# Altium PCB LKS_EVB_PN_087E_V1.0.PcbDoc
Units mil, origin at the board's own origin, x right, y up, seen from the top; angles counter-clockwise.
Board outline 1880 x 1275 mil, 2 copper layers (Top Layer, Bottom Layer); 38 components, 28 nets, 115 pads, 60 vias.
Unrouted connection lines stored in the file: 3.
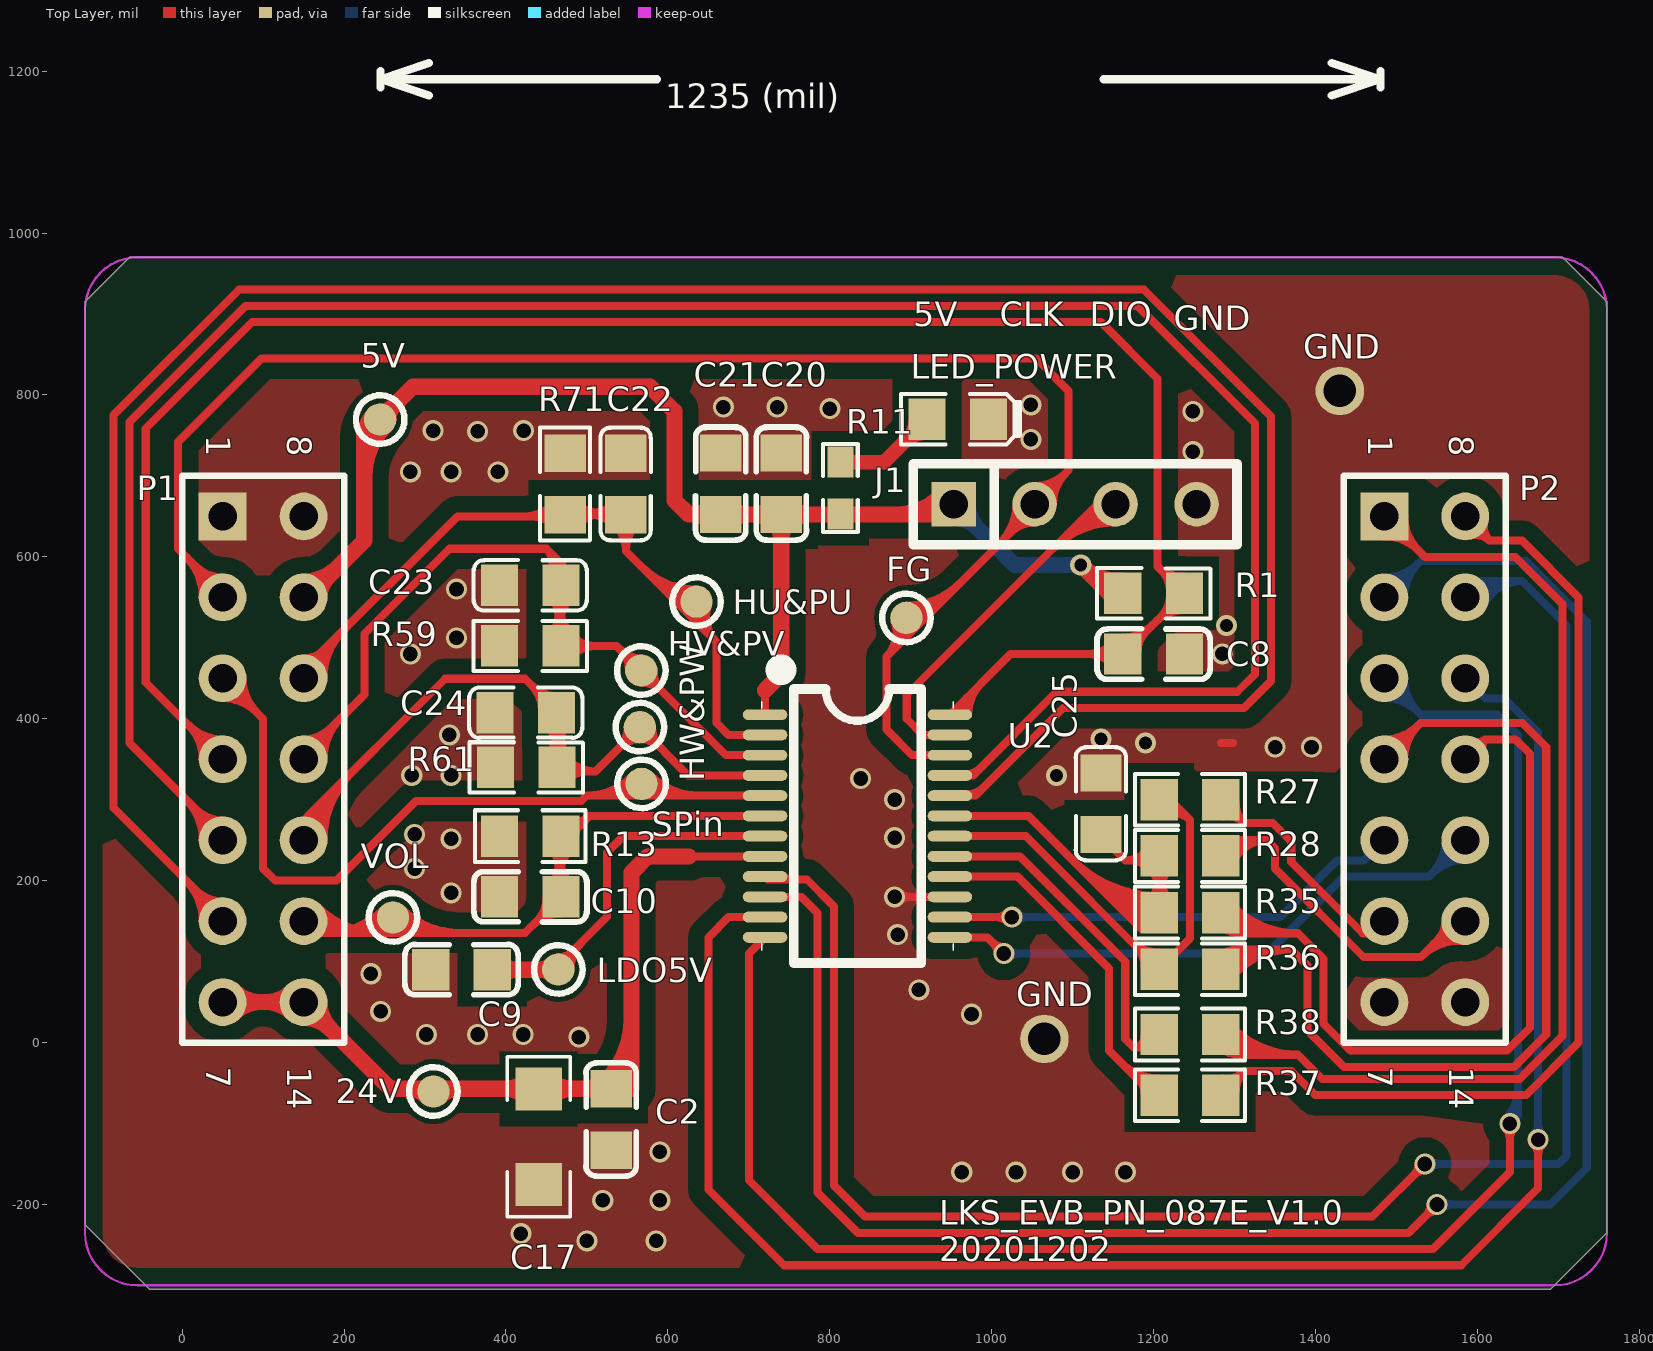
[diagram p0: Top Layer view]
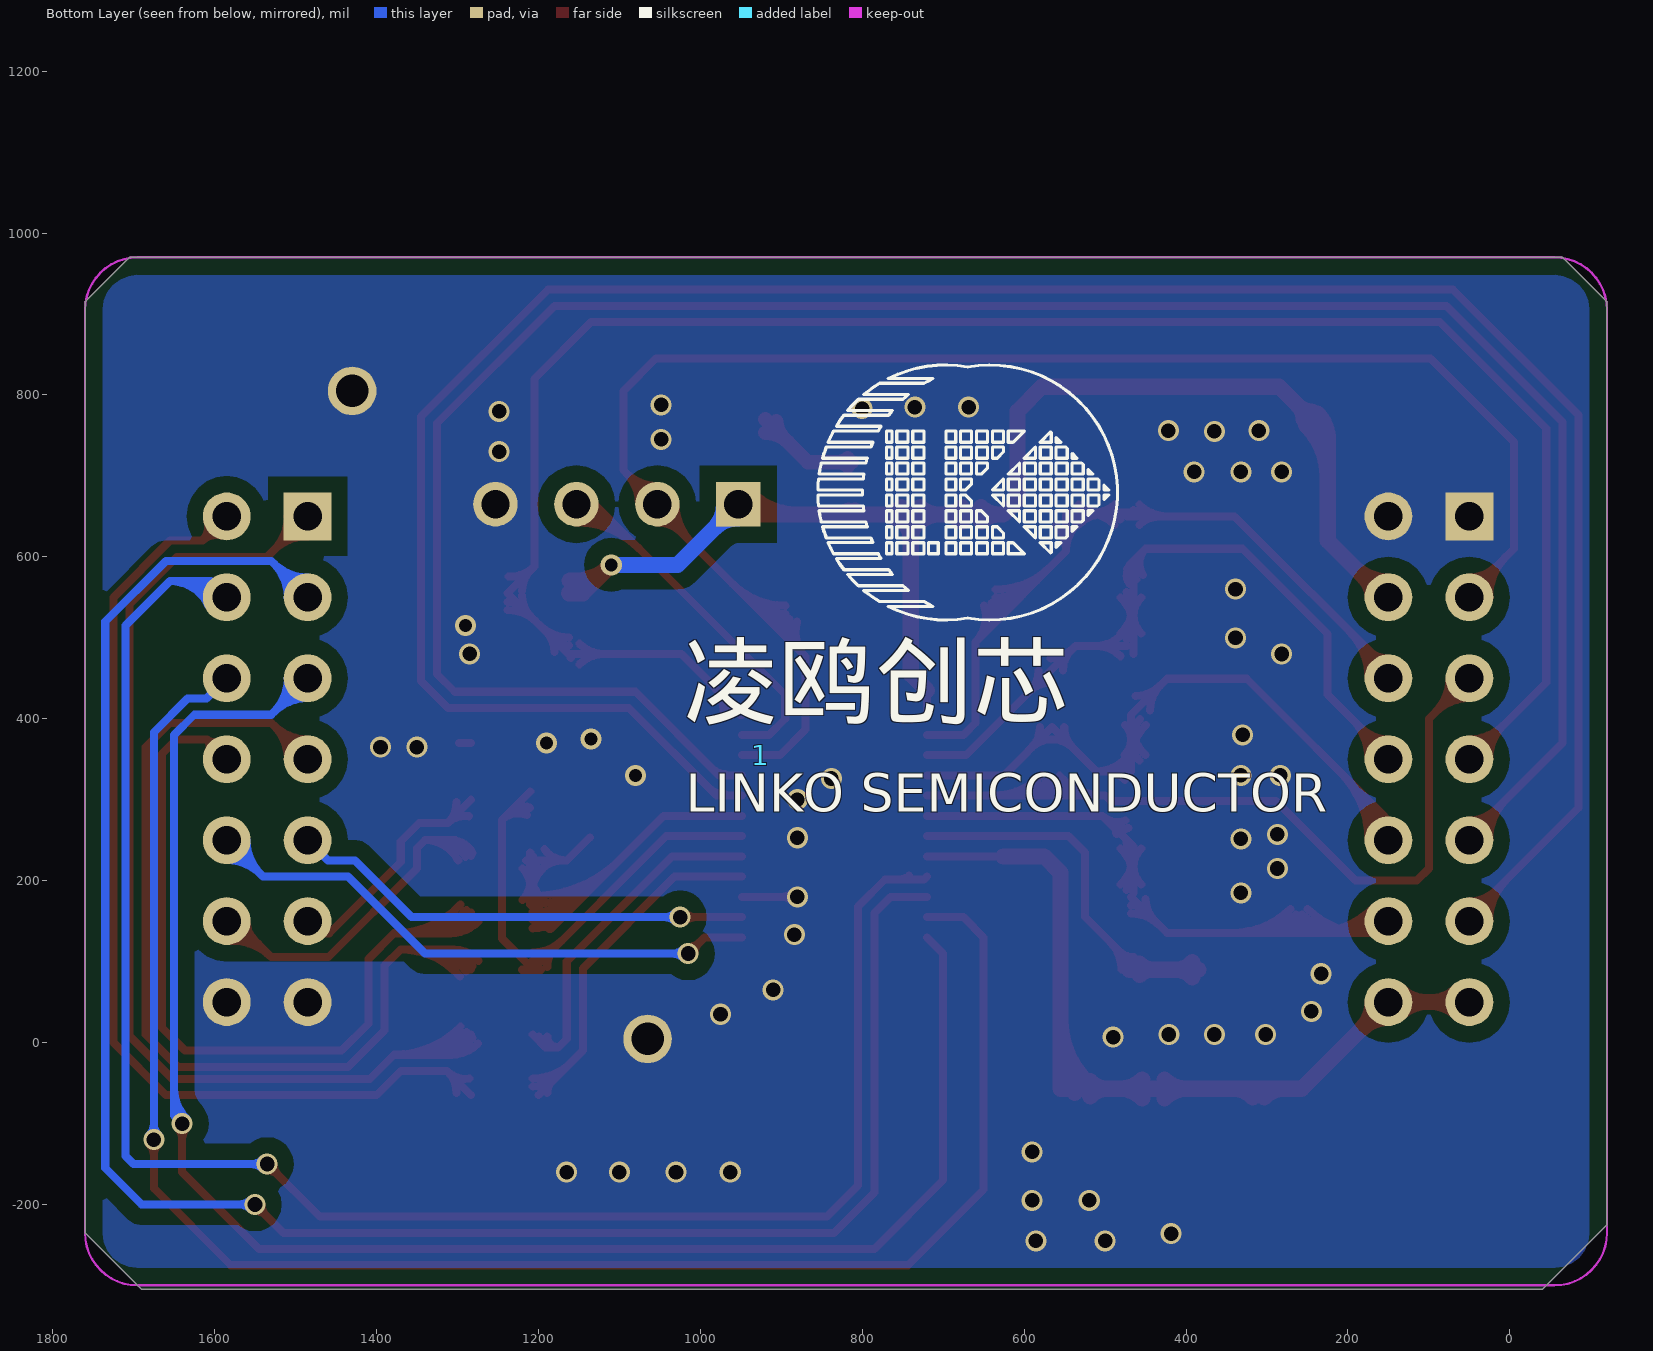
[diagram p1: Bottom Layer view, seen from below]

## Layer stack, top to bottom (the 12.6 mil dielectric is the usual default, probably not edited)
Top Layer: signal copper 1.4
Dielectric: dielectric 12.6, FR-4, Dk 4.8
Bottom Layer: signal copper 1.4

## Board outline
-120,-225 -40,-305 1690,-305 1760,-235 1760,915 1705,970 -65,970 -120,915

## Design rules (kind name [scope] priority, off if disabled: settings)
Clearance Clearance_1 [INPolygon] p1: gap=20
Clearance [All] p2: gap=10
ComponentClearance [All] p1: gap=0 collisioncheckmode=3 verticalgap=0 showdistances=FALSE
FabricationTestpoint [(IsPad And (OnTopLayer Or OnBottomLayer))] p1: side=3 testpointundercomponent=TRUE minsize=40 maxsize=100 preferedsize=60 minholesize=0 maxholesize=40 preferedholesize=32 testpointgrid=1 allowsidetop=TRUE allowsidebottom=TRUE usegrid=TRUE gridtolerance=0.01
PolygonConnect [All] p1: connectstyle=Direct reliefconductorwidth=20 reliefentries=4 polygonreliefangle="90 Angle"
RoutingVias [All] p1: holewidth=28 width=50 viastyle="Through Hole" minholewidth=28 minwidth=50 maxholewidth=28 maxwidth=50
SilkscreenOverComponentPads [All] p1: minsilkscreentomaskgap=10
SolderMaskExpansion [All] p1: expansion=4
Width [All] p1: maxlimit=300 minlimit=1 preferedwidth=10
25 further rules are at their usual default settings.

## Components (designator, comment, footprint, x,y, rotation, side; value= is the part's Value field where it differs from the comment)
1 "LKS_sign" LKS_LOGO2 925,355 r180 bottom
5V "TestP" TP-40 245,770 r0 top
24V "TestP" TP-40 310,-60 r90 top
C2 "100nF" 0805C 530,-95 r270 top
C8 "100nF" 0805C 1200,480 r0 top
C9 "1uF/10V" 0805C 345,90 r180 top
C10 "100nF" 0805C 430,180 r180 top
C17 "10uF/50V" 1206 440,-175 r90 top
C20 "100nF" 0805C 740.04,690.32 r90 top
C21 "10uF/10V" 0805C 665.04,690.32 r90 top
C22 "1nF/16V" 0805C 548,690 r270 top
C23 "1nF/16V" 0805C 430,565 r0 top
C24 "1nF/16V" 0805C 424.51,407.59 r0 top
C25 "100pF/50V" 0805C 1135,295 r270 top
FG "TestP" TP-40 895,525 r0 top
HU&PU "TestP" TP-40 635,545 r90 top
HV&PV "TestP" TP-40 566.72,460 r90 top
HW&PW "TestP" TP-40 565,390 r90 top
J1 "SWD" SIP4-2.5 1103,665 r0 top
LDO5V "TestP" TP-40 465,90 r270 top
LED_POWER "" 0805D 958,770 r0 top
P1 "Header 7X2A" HDR2X7_CEN 50,650 r270 top locked
P2 "Header 7X2A" HDR2X7_CEN 1485,650 r270 top locked
R1 "20K" 0805R 1200,555 r0 top
R11 "3.3K" 0603R 813,685 r270 top
R13 "3.3K" 0805R 430,255 r180 top
R27 "1K" 0805R 1245,300 r0 top
R28 "1K" 0805R 1245,230.59 r0 top
R35 "1K" 0805R 1245,160.59 r180 top
R36 "1K" 0805R 1245,90.59 r180 top
R37 "1K" 0805R 1245,-65 r180 top
R38 "1K" 0805R 1245,10 r180 top
R59 "20K 1%" 0805R 430,490 r0 top
R61 "3.3K" 0805R 425,340 r0 top
R71 "3.3K" 0805R 473,690 r270 top
SPin "TestP" TP-40 567.11,320 r90 top
U2 "LKS087E" LINKO-087 720,405 r270 top
VOL "TestP" TP-40 260,155 r90 top

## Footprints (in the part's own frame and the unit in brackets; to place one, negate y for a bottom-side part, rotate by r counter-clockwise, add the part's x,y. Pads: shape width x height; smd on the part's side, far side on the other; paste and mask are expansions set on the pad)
0603R [mil]
  rect 38x32 smd: 1(-32,0) 2(32,0)
  silkscreen extent -55,-22 55,22, body extent -31,-16 32,16, height 18
0805C [mil]
  rect 46x51.18 smd: 1(-38,0) 2(38,0)
  silkscreen extent -70,-31 70,31
0805D [mil]
  rect 46x51.18 smd: 1(-38,0) 2(38,0)
  silkscreen extent -70,-31 77,31, body extent -39,-25 39,25, height 22
0805R [mil]
  rect 46x51.18 smd: 1(-38,0) 2(38,0)
  silkscreen extent -70,-31 70,31, body extent -39,-25 39,25, height 22
1206 [mm]
  rect 1.35x1.45 smd: 1(-0.01,-0.01) 2(2.99,-0.01)
  silkscreen extent -1.02,-1 4,0.98
HDR2X7_CEN [mm] "Connector; Header; 7x2 Position"
  rect 1.5x1.5 hole 0.9: 1(0,0)
  round 1.5 hole 0.9: 2(2.54,0) 3(5.08,0) 4(7.62,0) 5(10.16,0) 6(12.7,0) 7(15.24,0) 8(0,2.54) 9(2.54,2.54) 10(5.08,2.54) 11(7.62,2.54) 12(10.16,2.54) 13(12.7,2.54) 14(15.24,2.54)
  silkscreen extent -1.27,-1.27 16.51,3.81
LINKO-087 [mm]
  oval 0.34x1.4 smd: 1(0,0) 2(0.635,0) 3(1.27,0) 4(1.905,0) 5(2.54,0) 6(3.175,0) 7(3.81,0) 8(4.445,0) 9(5.08,0) 10(5.715,0) 11(6.35,0) 12(6.985,0) 13(6.985,5.8) 14(6.35,5.8) 15(5.715,5.8) 16(5.08,5.8) 17(4.445,5.8) 18(3.81,5.8) 19(3.175,5.8) 20(2.54,5.8) 21(1.905,5.8) 22(1.27,5.8) 23(0.635,5.8) 24(0,5.8)
  silkscreen extent -1.51,-0.1 7.79,5.9
LKS_LOGO2 [mil] "标?"
  silkscreen extent 70,167 440,482
SIP4-2.5 [mil]
  rect 55x55 hole 35: 1(-150,0)
  round 55 hole 35: 2(-50,0) 3(50,0) 4(150,0)
  silkscreen extent -200,-50 200,50
TP-40 [mil] "测?"
  round 40 smd: 1(-0.39,-0.39)
  silkscreen extent -30,-30 30,30

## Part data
C2 C10 C17: library part CAP, "Capacitor"
C8 C20 C21 C22 C23 C24 C25: library part C, "Capacitor"
C9: library part C, "Cap"
J1: library part "Header 4", "Header, 4-Pin"
LED_POWER: library part LED2, "Typical RED, GREEN, YELLOW, AMBER GaAs LED"
P1 P2: "Header, 7-Pin, Dual row"
R1 R27 R28 R35 R36 R37 R38: library part RES2-1
R11 R13: library part Res2, "Resistor"
R59 R61 R71: library part RES/1

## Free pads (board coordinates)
  round 60 hole 40: 6(1065,4.61) 7(1430,805)

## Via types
v1: diameter 25.98, hole 17.99, Top Layer to Bottom Layer, 55 vias
v2: diameter 26, hole 16, Top Layer to Bottom Layer, 5 vias

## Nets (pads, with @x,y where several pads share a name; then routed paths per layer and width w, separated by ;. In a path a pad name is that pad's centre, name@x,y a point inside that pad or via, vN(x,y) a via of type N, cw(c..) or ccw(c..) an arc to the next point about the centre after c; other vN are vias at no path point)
5V: 5V.1 C20.1 C21.1 J1.1 P1.9 R1.1 R11.2 U2.1 | length 2374
  Top Layer w10: U2.1 720,435
  Top Layer w20: P1.9@150,569.53 ccw(c150,628.74) 191.87,586.87 ; P1.9@155,550 225,620 225,750 285,810 578,810 608,780 608,670 625.69,652.32 C21.1 C20.1 940.32,652.32 J1.1 ; P1.9@169.53,550 cw(c204.6,550) 179.8,574.8 ; 225,698.13 cw(c316.08,698.13) 5V.1@251.68,762.54 ; 225,746.41 cw(c267.8,746.41) 5V.1@237.54,776.68 ; 5V.1@234.61,769.61 cw(c210.46,769.61) 227.54,752.54 cw(c244.61,735.46) 5V.1@244.61,759.61 ; 5V.1@244.61,779.61 ccw(c244.61,803.75) 261.68,786.68 ccw(c278.75,769.61) 5V.1@254.61,769.61 ; C21.1@653.26,643.12 ccw(c631.06,620.93) 631.06,652.32 ccw(c631.06,683.7) C21.1@653.26,661.51 ; C21.1@676.82,643.12 cw(c699.01,620.93) 699.01,652.32 cw(c699.01,683.7) C21.1@676.82,661.51 ; 720,435 740,455 C20.1@740,652 ; C20.1@728.26,643.12 ccw(c706.06,620.93) 706.06,652.32 ccw(c706.06,683.7) C20.1@728.26,661.51 ; C20.1@730.85,643.12 cw(c708.75,621.03) 740,621.03 ; 740,620.84 cw(c771.52,620.84) C20.1@749.23,643.12 ; C20.1@751.82,643.12 cw(c774.01,620.93) 774.01,652.32 cw(c774.01,683.7) C20.1@751.82,661.51 ; 796.86,652.32 ccw(c796.86,669.14) R11.2@808.76,657.24 ; R11.2@817.24,657.24 ccw(c829.14,669.14) 829.14,652.32 ; 880.13,652.32 ccw(c880.13,737.87) J1.1@940.63,677.37 ; J1.1@928.41,652.32 ccw(c928.41,689.59) J1.1@954.77,663.23 ; R1.1@1161.22,570.57 cw(c1157.2,637.2) v2(1110,590) 1145,555 R1.1
  Bottom Layer w20: J1.1@953,647.5 cw(c953,605.25) 982.87,635.13 cw(c1012.75,665) J1.1@970.5,665 ; J1.1 1028,590 v2(1110,590)
24V_MCU: 24V.1 C2.1 C17.2 P1.7 P1.14 U2.8 | length 1574.5
  Top Layer w10: 625.69,230 U2.8
  Top Layer w20: P1.7 P1.14 257,-57 555,-57 555,210 575,230 625.69,230 ; P1.7@63.81,36.19 cw(c97.14,2.86) 97.14,50 cw(c97.14,97.14) P1.7@63.81,63.81 ; P1.14@136.19,36.19 ccw(c102.86,2.86) 102.86,50 ccw(c102.86,97.14) P1.14@136.19,63.81 ; P1.14@150,30.47 cw(c150,-16.67) 183.34,16.66 cw(c216.67,50) P1.14@169.53,50 ; 278.06,-57 cw(c278.06,-92.73) 24V.1@303.32,-67.46 ; 24V.1@317.46,-67.46 cw(c342.73,-92.73) 342.73,-57 ; 397.72,-57 cw(c397.72,-97.99) C17.2@426.71,-69 ; 399.1,-57 ccw(c399.1,-17.95) C17.2@426.71,-45.56 ; C17.2@454.08,-69 cw(c483.06,-97.99) 483.06,-57 ; C17.2@454.08,-45.56 ccw(c481.69,-17.95) 481.69,-57 ; C2.1@518.22,-66.19 ccw(c496.02,-88.38) 496.02,-57 ccw(c496.02,-25.62) C2.1@518.22,-47.81 ; C2.1@523.4,-47.81 ccw(c447.1,28.49) 555,28.49 ; C2.1@537.54,-61.95 ccw(c495.39,-19.8) 555,-19.8
FG: FG.1 J1.2 P1.2 U2.22 | length 2628
  Top Layer w10: 4.59,600.41 cw(c-45.81,550) P1.2@25.47,550 ; 16.66,588.34 ccw(c50,621.67) P1.2@50,574.53 ; 21.66,583.34 cw(c-11.67,550) P1.2@35.47,550 ; P1.2@55,550 -5,610 -5,741.86 98.14,845 1055,845 1095,805 1095,707 J1.2 ; FG.1@880.35,519.95 cw(c839.96,506.76) 870,476.72 ; 881.52,488.24 ccw(c857.33,512.43) FG.1@889.85,523.05 ; 893.04,499.76 ccw(c874.69,518.1) FG.1@899.36,526.16 ; FG.1@894.61,519.61 ccw(c894.61,563.75) 925.82,532.54 ; FG.1@894.61,529.61 ccw(c894.61,597.89) 942.89,549.61 ; FG.1@894.61,539.61 ccw(c894.61,632.03) 959.96,566.68 ; U2.22 901.72,355 870,386.72 870,476.72 ; 1010.85,617.57 ccw(c963.42,665) J1.2@1030.5,665 ; 1023.61,630.33 cw(c1053,600.94) J1.2@1053,642.5 ; 1027.92,634.64 ccw(c997.57,665) J1.2@1040.5,665 ; J1.2@1053,656.28 1049.57,656.28 870,476.72 ; J1.2@1053,677.5 ccw(c1053,707.68) 1074.34,686.34 ccw(c1095.68,665) J1.2@1065.5,665 ; J1.2@1053,687.5 ccw(c1053,741.82) 1091.41,703.41 ccw(c1129.82,665) J1.2@1075.5,665
G: P2.1 P2.4 P2.13 R28.2 R36.1 R38.1 | length 3916.6
  Top Layer w10: R36.1@1273.92,101.02 cw(c1304.45,74.66) R36.1@1304.45,115 ; R38.1@1274.37,-0.93 ccw(c1307.54,31.14) 1307.54,-15 ; R28.2@1281.22,234.09 cw(c1307.26,220.74) 1307.26,250 ; R36.1@1281.49,94.49 cw(c1326.3,55.79) 1326.3,115 ; R38.1@1281.56,6.02 ccw(c1331.12,53.94) 1331.12,-15 ; R38.1 1308,-15 ; R36.1 1307.41,115 ; R28.2 1302.41,250 1340,250 ; R38.1@1288.03,-9.87 cw(c1293.68,-29.32) 1308,-15 ; R36.1@1288.41,110.35 ccw(c1294.08,128.33) 1307.41,115 ; R38.1@1288.75,12.97 ccw(c1354.7,76.74) 1354.7,-15 ; R36.1@1289.05,87.95 cw(c1348.15,36.92) 1348.15,115 ; R28.2@1290.12,229.53 cw(c1323.63,212.34) 1323.63,250 ; R38.1@1295.94,19.92 ccw(c1378.28,99.53) 1378.28,-15 ; R36.1@1296.62,81.42 cw(c1370,18.06) 1370,115 ; R28.2@1299.02,224.96 cw(c1340,203.94) 1340,250 ; R36.1@1300.84,95.57 cw(c1323.76,98.65) 1307.41,115 ; R38.1@1300.88,5.37 ccw(c1325.56,2.56) 1308,-15 ; P2.4 1529.53,394.53 1655.47,394.53 1685,365 1685,10 1645,-30 1435,-30 1390,15 1390,95 1370,115 ; P2.4@1485,364.53 ccw(c1485,399.6) 1509.8,374.8 ccw(c1534.6,350) P2.4@1499.53,350 ; P2.4@1485,374.53 ccw(c1485,433.74) 1526.87,391.87 ccw(c1568.74,350) P2.4@1509.53,350 ; P2.1@1485,625.47 cw(c1485,566.26) 1526.87,608.13 cw(c1568.74,650) P2.1@1509.53,650 ; P2.1@1485,635.47 cw(c1485,600.4) 1509.8,625.2 cw(c1534.6,650) P2.1@1499.53,650 ; P2.1 1535,600 1646.72,600 1705,541.72 1705,8.28 1651.72,-45 1408.28,-45 1378.28,-15 ; 1545.02,120.97 cw(c1580.43,85.57) P2.13@1583.97,135.51 ; 1550.87,126.81 ccw(c1527.68,150) P2.13@1560.47,150 ; P2.13@1583.26,125.53 ccw(c1578.38,56.63) 1529.53,105.47 ; P2.13 1574.06,150 1529.53,105.47 ; 1307.41,115 1370,115 ; 1308,-15 1378.28,-15 ; 1340,250 1350,240 1350,215 1459.53,105.47 1529.53,105.47
GND: C2.2 C8.2 C9.2 C10.2 C17.1 C20.2 C21.2 C22.1 C23.1 C24.1 C25.1 J1.4 LED_POWER.2 P1.1 P1.8 P2.6 P2.7 P2.14 pad.6 pad.7 R13.2 R27.2 R59.1 R61.1 R71.1 U2.15 | length 462.5
  Top Layer w10: v1(880.13,180) U2.15 ; v1@885.78,174.35 cw(c899.42,160.71) 899.42,180 cw(c899.42,199.29) v1@885.78,185.65 ; R27.2 1311.82,271.18 ; 1283,370 1298.28,370 ; R27.2@1285.82,279.63 cw(c1290.53,249.89) 1311.82,271.18 ; R27.2@1301,297.37 ccw(c1337.93,297.3) 1311.82,271.18 ; P2.6 1470,135 1458.28,135 1370,223.28 1370,248.28 1347.1,271.18 1311.82,271.18
  other v1: 500,-245 585.43,-245 418.46,-235.9 519.51,-195 590,-195 963,-160 1030,-160 1100,-160 1165,-160 590,-135 490,6.74 301.58,10 365,10 421.08,10 975,35 245.17,38.57 910,65 233.18,85 883.69,133.45 332.17,185 287.2,215 332.24,251.63 880.13,253.02 287.2,257.11 880,300 838.02,326.18 283.58,330 332.17,330 1350,365 1395,365 330,380 281.87,480 1285,480.13 338.9,500 338.9,560 281.87,705 332.17,705 390,705 1248.44,730 1048.36,745 365,755 310,756 421.86,756 1248.44,779.74 800,783.04 668.41,785 735,785 1048.36,787.83
  other v2: 1080,330 1190,370 1135,375 1290,515
HU&PU: C22.2 HU&PU.1 P1.10 R71.2 U2.2 | length 1653.4
  Top Layer w10: P1.10@150,460 340,650 R71.2@473,650 ; P1.10@150,474.53 ccw(c150,509.6) 174.8,484.8 ; P1.10@164.53,450 cw(c223.74,450) 181.87,491.87 ; P1.10@174.53,450 cw(c257.88,450) 198.94,508.94 ; 422.13,650 ccw(c422.13,700.28) R71.2@457.68,664.73 ; 431.78,650 cw(c431.78,613.37) R71.2@457.68,639.27 ; 446.27,650 ccw(c446.27,676.14) R71.2@464.75,657.66 ; R71.2@463,655 C22.2@543,655 ; R71.2@481.25,646.34 cw(c502.15,625.44) 502.15,655 ; R71.2@488.32,639.27 cw(c526.29,601.3) C22.2@526.29,655 ; R71.2@488.32,664.73 ccw(c511.8,688.21) 511.8,655 ; R71.2@494.71,655 cw(c494.71,601.3) C22.2@532.68,639.27 ; 509.2,655 ccw(c509.2,688.21) C22.2@532.68,664.73 ; 512.57,651.32 cw(c516.35,637.22) C22.2@529.37,643.84 ; 518.85,655 cw(c518.85,625.44) C22.2@539.75,646.34 ; 519.7,653.23 ccw(c515.39,669.33) C22.2@529.82,661 ; C22.2@535.27,639.27 cw(c504.54,608.54) 548,608.54 cw(c591.46,608.54) C22.2@560.73,639.27 ; C22.2 548,607 660,495 ; 567.11,587.89 ccw(c635.39,656.17) HU&PU.1@635.39,559.61 ; 584.18,570.82 ccw(c635.39,622.03) HU&PU.1@635.39,549.61 ; 601.25,553.75 ccw(c635.39,587.89) HU&PU.1@635.39,539.61 ; HU&PU.1@630.66,546.22 ccw(c656.86,537.29) 637.29,517.71 ; HU&PU.1@640.13,542.99 ccw(c673.8,531.51) 648.64,506.36 ; HU&PU.1@649.59,539.77 ccw(c690.74,525.74) 660,495 ; U2.2 675,380 660,395 660,495
HV&PV: C23.2 HV&PV.1 P1.11 R59.2 U2.3 | length 1547.8
  Top Layer w10: P1.11@145,350 225,430 225,505 330,610 450,610 ; P1.11@150,374.53 ccw(c150,421.67) 183.34,388.34 ; P1.11@164.53,350 cw(c211.67,350) 178.34,383.34 ; P1.11@174.53,350 cw(c245.81,350) 195.41,400.41 ; C23.2@453.09,577.68 ccw(c431.97,591.97) 450,610 ; R59.2@455.27,505.32 ccw(c431.79,528.8) 465,528.8 ; C23.2@455.27,549.68 cw(c431.79,526.2) 465,526.2 ; C23.2@458.3,582.75 ccw(c450.46,595) 465,595 ; 458.57,601.43 cw(c442.19,585.05) C23.2@461.37,572.07 ; C23.2@459,546.82 cw(c450.67,532.39) 466.77,536.7 ; R59.2@465,480 465,595 ; R59.2@465,511.71 cw(c518.7,511.71) C23.2@480.73,549.68 ; 465,519.15 ccw(c494.56,519.15) R59.2@473.66,498.25 ; 465,535.85 cw(c494.56,535.85) C23.2@473.66,556.75 ; C23.2@465,543.29 ccw(c518.7,543.29) R59.2@480.73,505.32 ; 467.13,592.87 cw(c452.41,578.14) C23.2@469.66,566.47 ; 468.68,529.57 cw(c482.78,533.35) C23.2@476.16,546.37 ; C23.2@472.68,584.97 cw(c475.39,595) 465,595 ; R59.2@473,490 536.72,490 HV&PV.1 671.72,355 U2.3 ; R59.2@480.73,477.27 cw(c511.46,446.54) 511.46,490 cw(c511.46,533.46) R59.2@480.73,502.73 ; HV&PV.1@552.11,459.61 ccw(c515.9,459.61) 541.5,485.21 ccw(c567.11,510.82) HV&PV.1@567.11,474.61 ; HV&PV.1@567.11,444.61 cw(c567.11,408.39) 592.72,434 cw(c618.32,459.61) HV&PV.1@582.11,459.61 ; 450,610 465,595
HW&PW: C24.2 HW&PW.1 P1.12 R61.2 U2.4 | length 1542.5
  Top Layer w10: P1.12@144.53,250 cw(c190.25,250) 157.92,282.33 ; P1.12@154.53,250 cw(c224.39,250) 174.99,299.4 ; P1.12@155,242 155,279.41 325,449.41 423.59,449.41 468,405 468,335 510.79,335 ; P1.12@164.53,250 cw(c258.53,250) 192.06,316.47 ; P1.12@174.53,250 cw(c292.67,250) 209.13,333.54 ; 431.56,441.44 cw(c400.31,410.18) C24.2@444.51,410.18 ; 432.31,440.69 ccw(c462.51,470.89) C24.2@462.51,428.18 ; C24.2@449.78,392.27 cw(c405.8,348.29) R61.2@468,348.29 ; R61.2@450.27,355.32 ccw(c407.47,398.12) C24.2@468,398.12 ; C24.2@456.85,399.34 cw(c429.94,372.43) 468,372.43 ; R61.2@457.34,348.25 ccw(c431.62,373.98) 468,373.98 ccw(c494.38,373.98) R61.2@475.73,355.32 ; 463.07,379.71 cw(c477.05,375.96) C24.2@470.57,388.9 ; 468,374.8 cw(c492.71,374.8) C24.2@475.24,392.27 ; R61.2@468.78,342.94 ccw(c487.37,360.74) 487.37,335 ; R61.2@475.73,324.68 cw(c500.64,299.77) 500.64,335 ; R61.2@476,349.86 ccw(c510.78,383.14) 510.78,335 ; HW&PW.1@550.39,389.61 cw(c514.18,389.61) 539.79,364 cw(c565.39,338.39) 565.39,374.61 cw(c565.39,338.39) 591,364 cw(c616.61,389.61) HW&PW.1@580.39,389.61 ; U2.4 625,330 HW&PW.1 510.79,335
LDO5V: C9.1 LDO5V.1 U2.7 | length 622.1
  Top Layer w10: LDO5V.1@460,90.39 525,155.39 525,235 545,255 U2.7 ; LDO5V.1@464.61,105.39 ccw(c464.61,130.49) 482.35,112.74 ; LDO5V.1@469.61,90.39 cw(c492.8,90.39) 476.4,106.79 ; LDO5V.1@479.61,90.39 cw(c526.94,90.39) 493.47,123.86
  Top Layer w20: C9.1@385,90 LDO5V.1@470,90 ; C9.1@392.19,80.81 cw(c414.38,58.62) 414.38,90 cw(c414.38,121.38) C9.1@392.19,99.19 ; 439.51,90 ccw(c439.51,115.49) LDO5V.1@457.54,97.46 ; 441.41,90 cw(c441.41,67.2) LDO5V.1@457.54,83.32
NetLED_POWER_1: LED_POWER.1 R11.1 | length 209.1
  Top Layer w17.87: R11.1 867,717 LED_POWER.1 ; R11.1@817.99,712.01 cw(c830.05,699.95) 830.05,717 cw(c830.05,734.05) R11.1@817.99,721.99 ; 891.57,741.57 cw(c920,713.14) LED_POWER.1@920,753.35 ; LED_POWER.1@897.82,747.82 ccw(c878.24,767.41) LED_POWER.1@905.94,767.41
NRST: C8.1 P1.4 R1.2 U2.24 | length 2947.8
  Top Layer w10: P1.4@25.47,350 ccw(c-33.74,350) 8.13,391.87 ccw(c50,433.74) P1.4@50,374.53 ; P1.4@35.47,350 ccw(c0.4,350) 25.2,374.8 ccw(c50,399.6) P1.4@50,364.53 ; P1.4 -45,445 -45,758.43 86.57,890 1135,890 1205,820 1205,615 1205,588 ; U2.24 1023.35,480 C8.1@1160,480 ; U2.24@950.91,405 cw(c957.08,405) U2.24@952.71,409.37 ; U2.24@960.91,405 cw(c991.23,405) 969.79,426.44 ; U2.24@970.91,405 cw(c1025.37,405) 986.86,443.51 ; C8.1@1149.27,467.27 ccw(c1118.54,436.54) 1118.54,480 ccw(c1118.54,523.46) C8.1@1149.27,492.73 ; C8.1@1160,475 C8.1@1160,480 ; C8.1@1162,490.59 ccw(c1162,518.57) C8.1@1181.79,498.79 ; C8.1@1162,500.59 ccw(c1162,552.71) 1198.86,515.86 ; C8.1@1180,482.59 cw(c1214.79,482.59) 1190.19,507.19 ; 1202.85,519.85 cw(c1238,484.7) R1.2@1238,534.41 ; 1209.1,526.1 ccw(c1182.8,552.41) R1.2@1220,552.41 ; 1209.1,583.9 cw(c1182.8,557.59) R1.2@1220,557.59 ; R1.2@1219.92,536.92 cw(c1238,518.84) R1.2@1238,544.41 ; R1.2@1237.15,575.57 cw(c1235.12,618.12) 1205,588 ; C8.1@1160,480 C8.1 1163,480 R1.2 1205,588
OPA2_IN: R38.2 U2.17 | length 461
  Top Layer w10: U2.17 1035,230 1165,100 1165,4.61 1175.46,-5.86 ; R38.2@1185.55,-5.86 ccw(c1185.55,7.59) R38.2@1199,7.48 ; R38.2@1189,7.56 cw(c1175.47,7.68) 1175.47,-5.86 ; R38.2 1191.14,-5.86 1175.46,-5.86
OPA2_IP: R37.2 U2.16 | length 524.7
  Top Layer w10: U2.16 1031.72,205 1145,91.72 1145,-10 R37.2@1200,-65 ; 1159.9,-24.9 ccw(c1207,22.2) R37.2@1207,-44.41 ; 1176.97,-41.97 ccw(c1207,-11.94) R37.2@1207,-54.41 ; 1183.05,-48.05 cw(c1168.7,-62.41) R37.2@1189,-62.41
OPA3_IN: R27.1 R36.2 U2.18 | length 759.4
  Top Layer w10: U2.18 1015,255 1042,255 R36.2@1207,90 ; 1170.84,126.16 ccw(c1207,162.32) R36.2@1207,111.18 ; 1178.52,118.48 cw(c1153.22,93.18) R36.2@1189,93.18 ; R36.2@1187.91,109.09 ccw(c1207,128.17) R36.2@1207,101.18 ; R27.1@1210,310 1245,275 ; R27.1@1210.18,290.07 cw(c1218.96,269.77) 1234.59,285.41 ; R27.1@1214.15,280.89 cw(c1225.24,255.24) 1245,275 ; R36.2@1220,90 R36.2@1207,90 ; R36.2@1207,90 1196.72,90 R36.2 1207,90.79 1245,128.79 1245,275
OPA3_IP: C25.2 R28.1 R35.2 U2.19 | length 1184.4
  Top Layer w10: U2.19 1045.28,280 1185.14,140.14 1186.55,140.14 R35.2 ; 1099.63,225.66 ccw(c1207,333.03) R35.2@1207,181.18 ; 1116.7,208.58 ccw(c1207,298.89) R35.2@1207,171.18 ; 1133.77,191.51 ccw(c1207,264.74) R35.2@1207,161.18 ; C25.2@1136.45,253.55 1165,225 ; 1150.84,174.44 ccw(c1207,230.6) R35.2@1207,151.18 ; 1167.91,157.37 ccw(c1207,196.46) R35.2@1207,141.18 ; 1170.79,225 cw(c1170.79,191.79) 1194.27,215.27 cw(c1156.3,177.3) R35.2@1210,177.3 ; R28.1@1192.6,238.8 cw(c1165,259.5) 1165,225 ; R35.2@1194.27,175.91 ccw(c1156.3,213.88) R28.1@1210,213.88 ; R28.1@1199.37,211.7 cw(c1194.37,201.04) 1205.74,197.99 ; R35.2@1200,160.59 1210,170.59 R28.1@1210,225 ; R35.2@1201.34,168.84 ccw(c1180.44,189.74) 1210,189.74 ; R28.1@1201.34,222.34 cw(c1180.44,201.44) 1210,201.44 ; 1206.18,199.61 cw(c1226.54,194.15) R28.1@1216,212.41 ; R28.1 1215,225 R28.1@1210,225 ; 1210,191.79 cw(c1243.21,191.79) R28.1@1219.73,215.27 ; 1210,199.39 ccw(c1243.21,199.39) R35.2@1219.73,175.91 ; R28.1@1210,235 R28.1@1210,225 ; 1165,225 R28.1@1210,225
RXD: P1.6 U2.20 | length 3177.7
  Top Layer w10: 4.59,200.41 cw(c-45.81,150) P1.6@25.47,150 ; 16.66,188.34 ccw(c50,221.67) P1.6@50,174.53 ; 21.66,183.34 cw(c-11.67,150) P1.6@35.47,150 ; P1.6@55,150 -85,290 -85,775 70,930 1188.28,930 1345,773.28 1345,446.72 1311.63,413.35 1088.32,413.35 979.98,305 U2.20 ; U2.20@969.21,306.69 ccw(c969.21,336.77) 990.48,315.5
SPIN: P1.3 SPin.1 U2.5 | length 1358.3
  Top Layer w10: P1.3@50,425.47 cw(c50,366.26) 91.87,408.13 cw(c133.74,450) P1.3@74.53,450 ; P1.3@50,435.47 cw(c50,400.4) 74.8,425.2 cw(c99.6,450) P1.3@64.53,450 ; P1.3 100,400 100,215 115,200 190.51,200 288.79,298.28 493,298.28 499.72,305 ; 522.61,305 ccw(c522.61,361.19) SPin.1@563.84,323 ; 545.51,305 ccw(c545.51,339.98) SPin.1@571.17,316.21 ; SPin.1@556.5,329.8 cw(c499.72,382.4) 499.72,305 ; SPin.1@563.97,316.07 ccw(c590.69,342.8) 590.69,305 ; SPin.1@571.04,323.14 ccw(c614.84,366.94) 614.84,305 ; SPin.1@578.11,330.21 ccw(c638.98,391.08) 638.98,305 ; U2.5 499.72,305
SWDIO: J1.3 U2.23 | length 646.4
  Top Layer w10: U2.23 915,380 895,400 895,429.61 1130.39,665 J1.3 ; 1076,610.6 cw(c1153,533.6) J1.3@1153,642.5 ; 1093.07,627.68 cw(c1153,567.75) J1.3@1153,652.5 ; 1110.14,644.75 cw(c1153,601.89) J1.3@1153,662.5
TXD: P1.5 U2.21 | length 2954.6
  Top Layer w10: 4.59,300.41 cw(c-45.81,250) P1.5@25.47,250 ; 16.66,288.34 ccw(c50,321.67) P1.5@50,274.53 ; 21.66,283.34 cw(c-11.67,250) P1.5@35.47,250 ; P1.5@50,255 -65,370 -65,766.72 78.28,910 1180,910 1325,765 1325,455 1303.35,433.35 1080.04,433.35 976.69,330 U2.21 ; U2.21@969.21,331.69 ccw(c969.21,353.84) 984.87,338.18
UH: P2.9 U2.9 | length 2470
  Top Layer w10: U2.9 723.31,201.69 771.59,201.69 805,168.28 805,-176.72 843.28,-215 1470,-215 v1(1535,-150) ; U2.9@742.06,206.2 ccw(c752.94,217.07) 752.94,201.69 ; v1@1527.01,-150 cw(c1507.71,-150) 1521.36,-163.64 cw(c1535,-177.29) v1@1535,-157.99
  Bottom Layer w10: v1(1535,-150) 1700,-150 1710,-140 1710,515 1655,570 ; v1@1540.65,-155.65 cw(c1554.29,-169.29) 1554.29,-150 cw(c1554.29,-130.71) v1@1540.65,-144.35 ; P2.9@1580.04,552.32 cw(c1607.84,539.31) 1607.84,570 ; P2.9 1605,570 1655,570 ; P2.9@1589.1,548.08 cw(c1623.56,531.96) 1623.56,570 ; P2.9@1598.16,543.84 cw(c1639.28,524.6) 1639.28,570 ; P2.9@1607.22,539.6 cw(c1655,517.24) 1655,570
UL: P2.2 U2.10 | length 2605.6
  Top Layer w10: U2.10 765,180 785,160 785,-185 835,-235 1515,-235 v1(1550,-200) ; v1@1542.01,-200 cw(c1522.71,-200) 1536.36,-213.64 cw(c1550,-227.29) v1@1550,-207.99
  Bottom Layer w10: P2.2 1530,595 1660,595 1735,520 1735,-155 1690,-200 v1(1550,-200) ; P2.2@1485,564.53 ccw(c1485,599.6) 1509.8,574.8 ccw(c1534.6,550) P2.2@1499.53,550 ; P2.2@1485,574.53 ccw(c1485,633.74) 1526.87,591.87 ccw(c1568.74,550) P2.2@1509.53,550 ; v1@1555.65,-205.65 cw(c1569.29,-219.29) 1569.29,-200 cw(c1569.29,-180.71) v1@1555.65,-194.35
UX: P2.8 R37.1 | length 1336
  Top Layer w10: R37.1 1313,-35 ; R37.1@1285.22,-44.55 ccw(c1289.34,-11.34) 1313,-35 ; R37.1@1301,-62.41 cw(c1338.2,-62.41) 1311.9,-36.1 ; P2.8 1615,620 ; P2.8@1591.38,626.32 cw(c1597.73,602.73) 1615,620 ; P2.8@1608.68,643.62 ccw(c1632.27,637.27) 1615,620 ; 1313,-35 1370,-35 1400,-65 1660,-65 1725,0 1725,550 1655,620 1615,620
VH: P2.10 U2.11 | length 2236.6
  Top Layer w10: U2.11 675,155 650,130 650,-181.72 743.28,-275 1580,-275 1675,-180 v1(1675,-120) ; v1@1669.35,-125.65 cw(c1655.71,-139.29) 1675,-139.29 cw(c1694.29,-139.29) v1@1680.65,-125.65
  Bottom Layer w10: P2.10 1610,425 1633.28,425 1675,383.28 v1(1675,-120) ; v1@1669.35,-114.35 ccw(c1655.71,-100.71) 1675,-100.71 ccw(c1694.29,-100.71) v1@1680.65,-114.35
VL: P2.3 U2.12 | length 2304.4
  Top Layer w10: U2.12 700,110 700,-170 785,-255 1545,-255 1640,-160 v1(1640,-100) ; v1@1634.35,-105.65 cw(c1620.71,-119.29) 1640,-119.29 cw(c1659.29,-119.29) v1@1645.65,-105.65
  Bottom Layer w10: P2.3@1485,425.47 cw(c1485,366.26) 1526.87,408.13 cw(c1568.74,450) P2.3@1509.53,450 ; P2.3@1485,435.47 cw(c1485,400.4) 1509.8,425.2 cw(c1534.6,450) P2.3@1499.53,450 ; P2.3 1530,405 1625,405 1650,380 1650,-90 v1(1640,-100) ; v1@1634.35,-94.35 ccw(c1596.56,-56.56) 1650,-56.56 ; v1@1641.42,-101.42 ccw(c1620.71,-80.71) 1650,-80.71
VOL: C10.1 P1.13 R13.1 U2.6 VOL.1 | length 1646.8
  Top Layer w10: P1.13@150,155 169.41,135.59 423.59,135.59 C10.1 ; P1.13@153.2,153.2 ccw(c195.72,195.72) 195.72,135.59 ; P1.13@160.27,160.27 ccw(c219.86,219.86) 219.86,135.59 ; P1.13@167.34,167.34 ccw(c244,244) 244,135.59 ; 178.27,135.59 ccw(c178.27,236.73) VOL.1@249.79,165.21 ; 202.41,135.59 ccw(c202.41,212.59) VOL.1@256.86,158.14 ; 226.56,135.59 ccw(c226.56,188.44) VOL.1@263.93,151.07 ; VOL.1@249.79,144 ccw(c270.09,164.3) 270.09,135.59 ; 250.7,135.59 ccw(c250.7,164.3) VOL.1@271,144 ; VOL.1@256.86,151.07 ccw(c294.23,188.44) 294.23,135.59 ; VOL.1@263.93,158.14 ccw(c318.37,212.59) 318.37,135.59 ; VOL.1@271,165.21 ccw(c342.52,236.73) 342.52,135.59 ; 432.85,144.85 cw(c468,109.7) C10.1@468,159.41 ; 439.1,151.1 ccw(c412.8,177.41) C10.1@450,177.41 ; C10.1@449.92,161.92 cw(c468,143.84) C10.1@468,169.41 ; C10.1@455.27,195.32 ccw(c431.79,218.8) 465,218.8 ; R13.1@455.27,239.68 cw(c431.79,216.2) 465,216.2 ; R13.1@459,236.82 cw(c450.67,222.39) 466.77,226.7 ; C10.1@465,185 465,242 503,280 ; C10.1@465,201.71 cw(c518.7,201.71) R13.1@480.73,239.68 ; 465,209.15 ccw(c494.56,209.15) C10.1@473.66,188.25 ; 465,225.85 cw(c494.56,225.85) R13.1@473.66,246.75 ; R13.1@465,233.29 ccw(c518.7,233.29) C10.1@480.73,195.32 ; 468.68,219.57 cw(c482.78,223.35) R13.1@476.16,236.37 ; R13.1@471.01,265 ccw(c478.4,283.25) 492.33,269.33 ; R13.1@474.76,274.27 ccw(c484.56,298.44) 503,280 ; R13.1@486,257.59 cw(c499.06,257.59) R13.1@489.82,266.82 ; U2.6 503,280
VX: P2.11 R35.1 | length 1284.2
  Top Layer w10: R35.1@1274.29,149.75 ccw(c1308.56,182.2) 1308.56,135 ; R35.1@1281.55,156.63 ccw(c1331.8,204.2) 1331.8,135 ; R35.1 1308.59,135 ; R35.1@1287.66,140.61 cw(c1293.26,119.67) 1308.59,135 ; R35.1@1288.81,163.5 ccw(c1355.04,226.21) 1355.04,135 ; R35.1@1296.07,170.38 ccw(c1378.28,248.21) 1378.28,135 ; R35.1@1300.92,156.31 ccw(c1327.39,153.8) 1308.59,135 ; P2.11 1609.53,374.53 ; P2.11@1595.57,372.13 ccw(c1600.86,383.2) 1609.53,374.53 ; P2.11@1607.13,360.57 cw(c1618.2,365.86) 1609.53,374.53 ; 1308.59,135 1378.28,135 ; 1378.28,135 1410,103.28 1410,23.28 1443.28,-10 1636.72,-10 1665,18.28 1665,356.72 1647.19,374.53 1609.53,374.53
WH: P2.12 U2.13 | length 911.6
  Top Layer w10: U2.13 995,130 v1(1015,110) ; v1@1007.01,110 ccw(c987.71,110) 1001.36,123.64 ccw(c1015,137.29) v1@1015,117.99
  Bottom Layer w10: v1(1015,110) 1340,110 1435,205 1540,205 P2.12 ; v1@1020.65,104.35 cw(c1034.29,90.71) 1034.29,110 cw(c1034.29,129.29) v1@1020.65,115.65 ; P2.12@1560.47,250 cw(c1501.26,250) 1543.13,208.13 cw(c1585,166.26) P2.12@1585,225.47 ; P2.12@1570.47,250 cw(c1535.4,250) 1560.2,225.2 cw(c1585,200.4) P2.12@1585,235.47
WL: P2.5 U2.14 | length 636.6
  Top Layer w10: U2.14 v1(1025,155) ; v1@1019.35,149.35 ccw(c1005.71,135.71) 1005.71,155 ccw(c1005.71,174.29) v1@1019.35,160.65
  Bottom Layer w10: v1(1025,155) 1356.72,155 1426.72,225 1460,225 P2.5 ; v1@1030.65,149.35 cw(c1044.29,135.71) 1044.29,155 cw(c1044.29,174.29) v1@1030.65,160.65

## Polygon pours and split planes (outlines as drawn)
GND on Top Layer "Bottom Layer-No Net" (solid, remove dead copper, pour order 3): -125,970 -125,-300 1750,-300 1755,-295 1755,970
GND on Bottom Layer "Bottom Layer-No Net" (solid, remove dead copper, pour order 4): -120,970 -120,-300 1755,-300 1760,-295 1760,970

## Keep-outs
Keep-Out Layer:
  lines w2.99: -120,-235 ccw(c-55,-235) -55,-300 ; -120,905 cw(c-55,905) -55,970 ; 1695,-300 ccw(c1695,-235) 1760,-235 ; 1695,970 cw(c1695,905) 1760,905
  lines w3: -120,-235 -120,905 ; -55,-300 1695,-300 ; -55,970 1695,970 ; 1760,-235 1760,905

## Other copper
Top Layer:
  pour cut-out: 1253,335 1385,335 1515,330 1583.26,335.11 1583.26,125.53 1555.86,125.53 1545,114.68 1542.96,116.72 1321.39,116.72 1253,225
Bottom Layer:
  pour cut-out: 1395,193.28 1566.72,193.28 1585,175 1585,100.05 1362.77,100.05 1352.81,110

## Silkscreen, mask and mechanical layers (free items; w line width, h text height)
Top Overlay:
  lines w10: 245,1180 245,1200 ; 305,1170 245,1190 ; 305,1210 245,1190 ; 586.58,1190 245,1190 ; 1138.42,1190 1480,1190 ; 1420,1170 1480,1190 ; 1420,1210 1480,1190 ; 1480,1180 1480,1200
  text "1235 (mil)" at 596.58,1154.01 h30
  text "5V" at 903,885 h30
  text "CLK" at 1010,885 h30
  text "DIO" at 1121.06,885 h30
  text "GND" at 1225,880 h30
  text "GND" at 1385,845 h30
  text "GND" at 1030,45 h30
  text "LKS_EVB_PN_087E_V1.0" at 935,-225 h30
  text "20201202" at 935,-270 h30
